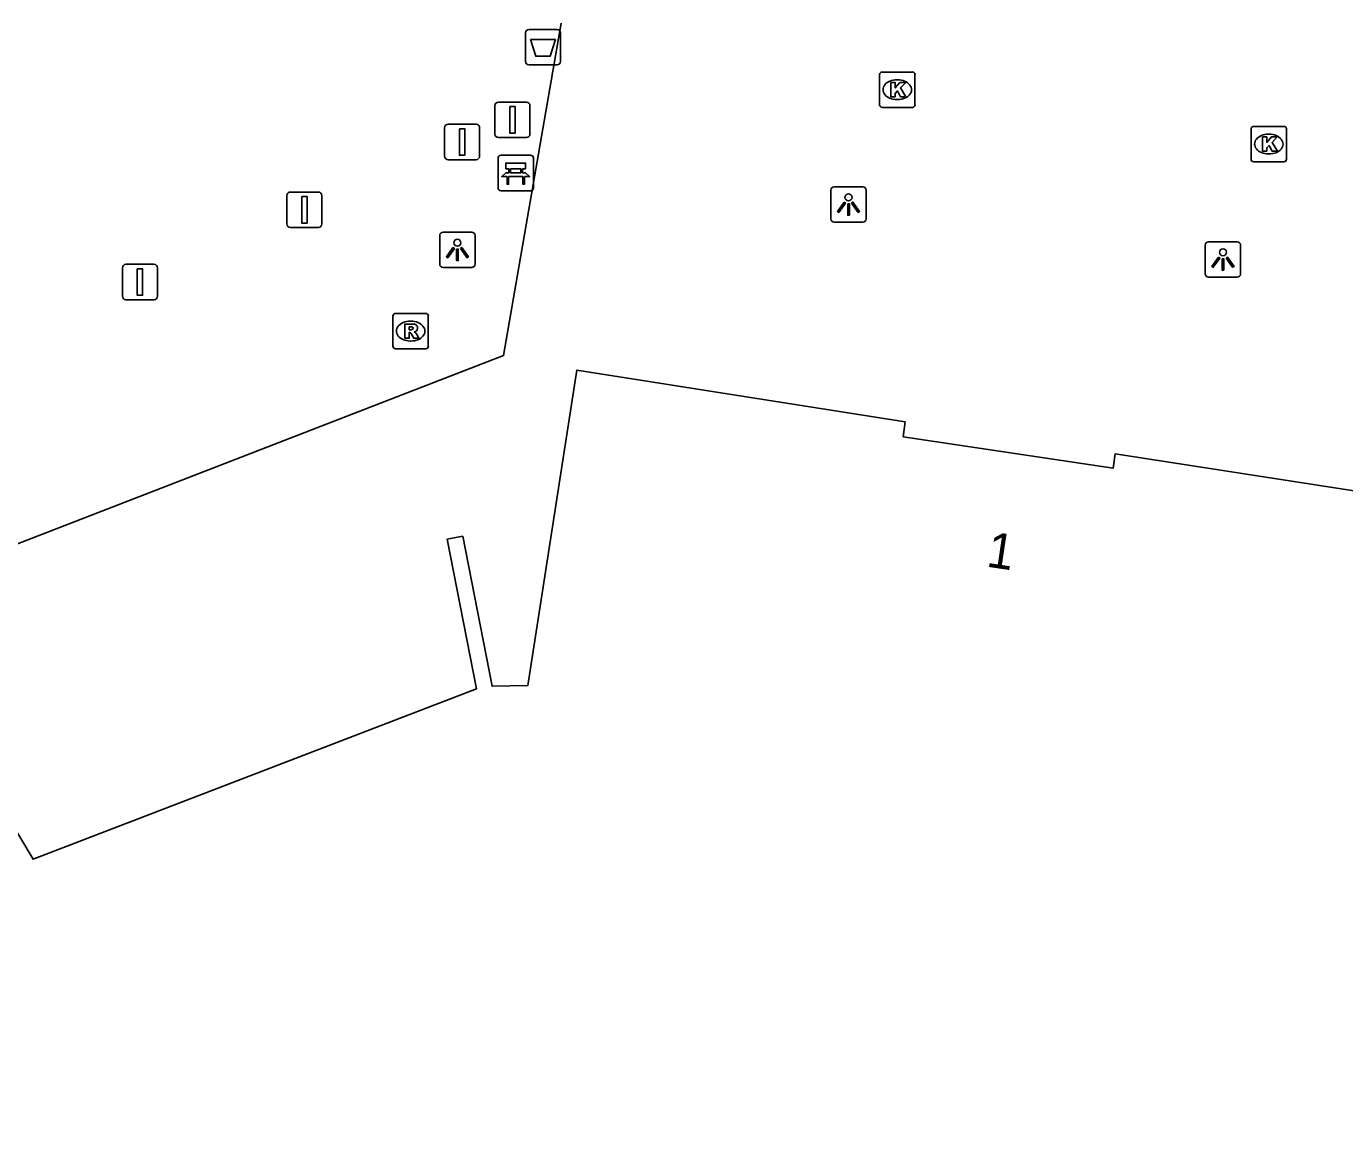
# Model space of a CAD drawing. Extents: x 161094 to 161705, y 379509 to 380907.
# Drawn here: x 161518.54 to 161555.75, y 380401.06 to 380432.35 of the extents above; entities that cross this region are included whole.
import ezdxf

# ---------------------------------------------------------------- set-up
doc = ezdxf.new("R2010")
doc.units = 0
for name, color, linetype in [('IMGEO_Afsluitpaal', 7, 'Continuous'), ('IMGEO_Afvalbak', 7, 'Continuous'), ('IMGEO_Bank', 7, 'Continuous'), ('IMGEO_Kolk', 7, 'Continuous'), ('IMGEO_Lichtpunt', 7, 'Continuous'), ('IMGEO_Pand', 7, 'Continuous'), ('IMGEO_Pand_nummerreeks', 7, 'Continuous'), ('IMGEO_Rioolput', 7, 'Continuous'), ('IMGEO_Vlaggenmast', 7, 'Continuous'), ('IMGEO_Voetpad_open', 7, 'Continuous')]:
    doc.layers.add(name, color=color, linetype=linetype)

msp = doc.modelspace()

# ---------------------------------------------------------------- linework, layer by layer
at = {"layer": 'IMGEO_Afsluitpaal'}
for p, q in [((161531.863, 380430.213), (161532.653, 380430.213)), ((161532.653, 380430.213), (161531.863, 380430.213)), ((161531.763, 380429.313), (161531.763, 380430.113)), ((161531.763, 380430.113), (161531.763, 380429.313)), ((161532.753, 380430.113), (161532.753, 380429.313)), ((161532.753, 380429.313), (161532.753, 380430.113)), ((161532.653, 380429.213), (161531.863, 380429.213)), ((161531.863, 380429.213), (161532.653, 380429.213))]:
    msp.add_line(p, q, dxfattribs=at)
msp.add_lwpolyline([(161532.183, 380430.088), (161532.333, 380430.088), (161532.333, 380429.338), (161532.183, 380429.338), (161532.183, 380430.088)], dxfattribs=at)
for centre, start, end in [((161531.863, 380430.113), 90, 180), ((161531.863, 380430.113), 90, 180), ((161532.653, 380430.113), 0, 90), ((161532.653, 380430.113), 360, 90), ((161531.863, 380429.313), 180, 270), ((161531.863, 380429.313), 180, 270), ((161532.653, 380429.313), 270, 0), ((161532.653, 380429.313), 270, 0)]:
    msp.add_arc(centre, 0.1, start, end, dxfattribs=at)
at = {"layer": 'IMGEO_Afvalbak'}
for p, q in [((161532.626, 380431.365), (161532.626, 380432.165)), ((161532.626, 380432.165), (161532.626, 380431.365)), ((161532.726, 380432.265), (161533.516, 380432.265)), ((161533.516, 380432.265), (161532.726, 380432.265)), ((161533.616, 380432.165), (161533.616, 380431.365)), ((161533.616, 380431.365), (161533.616, 380432.165)), ((161533.516, 380431.265), (161532.726, 380431.265)), ((161532.726, 380431.265), (161533.516, 380431.265))]:
    msp.add_line(p, q, dxfattribs=at)
msp.add_lwpolyline([(161532.769, 380431.979), (161533.473, 380431.979), (161533.324, 380431.509), (161532.918, 380431.509), (161532.769, 380431.979)], dxfattribs=at)
for centre, start, end in [((161532.726, 380432.165), 90, 180), ((161532.726, 380432.165), 90, 180), ((161533.516, 380432.165), 0, 90), ((161533.516, 380432.165), 360, 90), ((161532.726, 380431.365), 180, 270), ((161532.726, 380431.365), 180, 270), ((161533.516, 380431.365), 270, 0), ((161533.516, 380431.365), 270, 0)]:
    msp.add_arc(centre, 0.1, start, end, dxfattribs=at)
at = {"layer": 'IMGEO_Bank'}
for p, q in [((161531.926, 380428.713), (161532.767, 380428.713)), ((161532.767, 380428.713), (161531.926, 380428.713)), ((161531.851, 380427.788), (161531.851, 380428.629)), ((161531.851, 380428.629), (161531.851, 380427.788)), ((161532.16, 380428.219), (161532.16, 380428.325)), ((161532.204, 380428.325), (161532.204, 380428.219)), ((161532.492, 380428.331), (161532.21, 380428.331)), ((161532.498, 380428.219), (161532.498, 380428.325)), ((161532.542, 380428.325), (161532.542, 380428.219)), ((161532.851, 380428.638), (161532.851, 380427.797)), ((161532.851, 380427.797), (161532.851, 380428.638)), ((161532.548, 380428.111), (161532.155, 380428.111)), ((161532.21, 380428.213), (161532.492, 380428.213)), ((161532.776, 380427.713), (161531.935, 380427.713)), ((161531.935, 380427.713), (161532.776, 380427.713))]:
    msp.add_line(p, q, dxfattribs=at)
for points in [[(161532.154, 380428.331), (161532.068, 380428.331), (161532.068, 380428.492), (161532.631, 380428.492), (161532.631, 380428.331), (161532.548, 380428.331)], [(161532.098, 380428.111), (161531.956, 380428.111), (161532.068, 380428.213), (161532.154, 380428.213)], [(161532.148, 380428.104), (161532.148, 380427.897), (161532.105, 380427.897), (161532.105, 380428.104)], [(161532.548, 380428.213), (161532.631, 380428.213), (161532.743, 380428.111), (161532.604, 380428.111)], [(161532.598, 380428.104), (161532.598, 380427.897), (161532.554, 380427.897), (161532.554, 380428.104)]]:
    msp.add_lwpolyline(points, dxfattribs=at)
for centre, radius, start, end in [((161531.929, 380428.635), 0.0779, 92.4484, 184.2845), ((161531.929, 380428.635), 0.0779, 92.4484, 184.2845), ((161532.773, 380428.635), 0.0779, 2.4484, 94.2845), ((161532.773, 380428.635), 0.0779, 2.4484, 94.2845), ((161532.153, 380428.324), 0.00671, 2.8957, 87.1043), ((161532.21, 380428.324), 0.00671, 92.8957, 177.1043), ((161532.492, 380428.324), 0.00671, 2.8957, 87.1043), ((161532.549, 380428.324), 0.00671, 92.8957, 177.1043), ((161532.098, 380428.104), 0.00671, 2.8957, 87.1043), ((161532.155, 380428.104), 0.00671, 92.8957, 177.1043), ((161532.153, 380428.22), 0.00671, 272.8957, 357.1043), ((161532.21, 380428.22), 0.00671, 182.8957, 267.1043), ((161532.492, 380428.22), 0.00671, 272.8957, 357.1043), ((161532.549, 380428.22), 0.00671, 182.8957, 267.1043), ((161532.547, 380428.104), 0.00671, 2.8957, 87.1043), ((161532.604, 380428.104), 0.00671, 92.8957, 177.1043), ((161531.929, 380427.791), 0.0779, 182.4484, 274.2845), ((161531.929, 380427.791), 0.0779, 182.4484, 274.2845), ((161532.773, 380427.791), 0.0779, 272.4484, 4.2845), ((161532.773, 380427.791), 0.0779, 272.4484, 4.2845)]:
    msp.add_arc(centre, radius, start, end, dxfattribs=at)
at = {"layer": 'IMGEO_Kolk'}
for p, q in [((161542.621, 380430.138), (161542.621, 380430.99)), ((161542.696, 380431.064), (161543.548, 380431.064)), ((161543.622, 380430.99), (161543.622, 380430.138)), ((161543.109, 380430.844), (161543.134, 380430.844)), ((161543.132, 380430.284), (161543.107, 380430.284)), ((161543.548, 380430.064), (161542.696, 380430.064)), ((161553.11, 380428.603), (161553.11, 380429.455)), ((161553.185, 380429.529), (161554.037, 380429.529)), ((161554.111, 380429.455), (161554.111, 380428.603)), ((161553.598, 380429.309), (161553.623, 380429.309)), ((161553.621, 380428.749), (161553.596, 380428.749)), ((161554.037, 380428.529), (161553.185, 380428.529))]:
    msp.add_line(p, q, dxfattribs=at)
for points in [[(161542.621, 380430.138), (161542.621, 380430.99)], [(161542.696, 380431.064), (161543.548, 380431.064)], [(161543.622, 380430.99), (161543.622, 380430.138)], [(161542.942, 380430.764), (161543.065, 380430.764), (161543.065, 380430.613), (161543.195, 380430.764), (161543.359, 380430.764), (161543.213, 380430.613), (161543.366, 380430.364), (161543.214, 380430.364), (161543.129, 380430.528), (161543.065, 380430.461), (161543.065, 380430.364), (161542.942, 380430.364), (161542.942, 380430.764)], [(161543.548, 380430.064), (161542.696, 380430.064)], [(161553.11, 380428.603), (161553.11, 380429.455)], [(161553.185, 380429.529), (161554.037, 380429.529)], [(161554.111, 380429.455), (161554.111, 380428.603)], [(161553.431, 380429.229), (161553.554, 380429.229), (161553.554, 380429.078), (161553.684, 380429.229), (161553.848, 380429.229), (161553.702, 380429.078), (161553.855, 380428.829), (161553.703, 380428.829), (161553.618, 380428.993), (161553.554, 380428.926), (161553.554, 380428.829), (161553.431, 380428.829), (161553.431, 380429.229)], [(161554.037, 380428.529), (161553.185, 380428.529)]]:
    msp.add_lwpolyline(points, dxfattribs=at)
for centre, start, end in [((161542.698, 380430.988), 91.552, 178.448), ((161542.698, 380430.988), 91.552, 178.448), ((161543.546, 380430.988), 1.552, 88.448), ((161543.546, 380430.988), 1.552, 88.448), ((161542.698, 380430.14), 181.552, 268.448), ((161542.698, 380430.14), 181.552, 268.448), ((161543.546, 380430.14), 271.552, 358.448), ((161543.546, 380430.14), 271.552, 358.448), ((161553.187, 380429.453), 91.552, 178.448), ((161553.187, 380429.453), 91.552, 178.448), ((161554.035, 380429.453), 1.552, 88.448), ((161554.035, 380429.453), 1.552, 88.448), ((161553.187, 380428.605), 181.552, 268.448), ((161553.187, 380428.605), 181.552, 268.448), ((161554.035, 380428.605), 271.552, 358.448), ((161554.035, 380428.605), 271.552, 358.448)]:
    msp.add_arc(centre, 0.0765, start, end, dxfattribs=at)
for centre, major_axis, ratio, start_param, end_param in [((161543.108, 380430.564), (-0.387, 0.002), 0.722429, 4.712389, 7.853982), ((161543.133, 380430.564), (-0.39, 0.002), 0.717154, 1.570796, 4.712389), ((161553.597, 380429.029), (-0.387, 0.002), 0.722429, 4.712389, 7.853982), ((161553.622, 380429.029), (-0.39, 0.002), 0.717154, 1.570796, 4.712389)]:
    msp.add_ellipse(centre, major_axis=major_axis, ratio=ratio, start_param=start_param, end_param=end_param, dxfattribs=at)
at = {"layer": 'IMGEO_Lichtpunt'}
for p, q in [((161541.246, 380427.727), (161541.246, 380426.92)), ((161541.246, 380427.727), (161541.246, 380426.92)), ((161542.148, 380427.822), (161541.34, 380427.822)), ((161542.148, 380427.822), (161541.34, 380427.822)), ((161542.242, 380426.92), (161542.242, 380427.727)), ((161542.242, 380426.92), (161542.242, 380427.727)), ((161541.34, 380426.826), (161542.148, 380426.826)), ((161541.34, 380426.826), (161542.148, 380426.826)), ((161531.107, 380426.541), (161530.299, 380426.541)), ((161531.107, 380426.541), (161530.299, 380426.541)), ((161530.205, 380426.446), (161530.205, 380425.639)), ((161530.205, 380426.446), (161530.205, 380425.639)), ((161531.201, 380425.639), (161531.201, 380426.446)), ((161531.201, 380425.639), (161531.201, 380426.446)), ((161551.818, 380426.176), (161551.818, 380425.369)), ((161551.818, 380426.176), (161551.818, 380425.369)), ((161552.72, 380426.271), (161551.912, 380426.271)), ((161552.72, 380426.271), (161551.912, 380426.271)), ((161552.814, 380425.369), (161552.814, 380426.176)), ((161552.814, 380425.369), (161552.814, 380426.176)), ((161530.299, 380425.545), (161531.107, 380425.545)), ((161530.299, 380425.545), (161531.107, 380425.545)), ((161551.912, 380425.275), (161552.72, 380425.275)), ((161551.912, 380425.275), (161552.72, 380425.275))]:
    msp.add_line(p, q, dxfattribs=at)
for points in [[(161541.62, 380427.391), (161541.659, 380427.363), (161541.471, 380427.101), (161541.433, 380427.128), (161541.62, 380427.391)], [(161541.722, 380427.343), (161541.769, 380427.343), (161541.769, 380427.021), (161541.722, 380427.021), (161541.722, 380427.343)], [(161541.832, 380427.363), (161541.87, 380427.39), (161542.057, 380427.128), (161542.018, 380427.1), (161541.832, 380427.363)], [(161530.579, 380426.11), (161530.618, 380426.082), (161530.43, 380425.82), (161530.392, 380425.847), (161530.579, 380426.11)], [(161530.791, 380426.082), (161530.829, 380426.109), (161531.016, 380425.847), (161530.977, 380425.819), (161530.791, 380426.082)], [(161530.681, 380426.062), (161530.728, 380426.062), (161530.728, 380425.74), (161530.681, 380425.74), (161530.681, 380426.062)], [(161552.192, 380425.84), (161552.231, 380425.812), (161552.043, 380425.55), (161552.005, 380425.577), (161552.192, 380425.84)], [(161552.294, 380425.792), (161552.341, 380425.792), (161552.341, 380425.47), (161552.294, 380425.47), (161552.294, 380425.792)], [(161552.404, 380425.812), (161552.442, 380425.839), (161552.629, 380425.577), (161552.59, 380425.549), (161552.404, 380425.812)]]:
    msp.add_lwpolyline(points, dxfattribs=at)
for centre in [(161541.745, 380427.525), (161530.704, 380426.244), (161552.317, 380425.974)]:
    msp.add_circle(centre, 0.0994, dxfattribs=at)
for centre, start, end in [((161541.34, 380427.727), 90, 180), ((161541.34, 380427.727), 90, 180), ((161542.148, 380427.727), 0, 90), ((161542.148, 380427.727), 0, 90), ((161541.34, 380426.92), 180, 270), ((161541.34, 380426.92), 180, 270), ((161542.148, 380426.92), 270, 0), ((161542.148, 380426.92), 270, 360), ((161530.299, 380426.446), 90, 180), ((161530.299, 380426.446), 90, 180), ((161531.107, 380426.446), 0, 90), ((161531.107, 380426.446), 0, 90), ((161551.912, 380426.176), 90, 180), ((161551.912, 380426.176), 90, 180), ((161552.72, 380426.176), 0, 90), ((161552.72, 380426.176), 0, 90), ((161530.299, 380425.639), 180, 270), ((161530.299, 380425.639), 180, 270), ((161531.107, 380425.639), 270, 0), ((161531.107, 380425.639), 270, 360), ((161551.912, 380425.369), 180, 270), ((161551.912, 380425.369), 180, 270), ((161552.72, 380425.369), 270, 0), ((161552.72, 380425.369), 270, 360)]:
    msp.add_arc(centre, 0.0946, start, end, dxfattribs=at)
at = {"layer": 'IMGEO_Pand'}
msp.add_lwpolyline([(161572.534, 380403.556), (161572.222, 380403.897), (161570.561, 380402.435), (161568.999, 380401.06), (161558.595, 380409.43), (161560.648, 380413.202), (161560.248, 380413.425), (161558.15, 380409.628), (161557.225, 380409.976), (161558.567, 380418.844), (161549.278, 380420.286), (161549.217, 380419.881), (161543.293, 380420.766), (161543.349, 380421.185), (161534.077, 380422.646), (161532.695, 380413.746), (161531.682, 380413.721), (161530.856, 380417.957), (161530.412, 380417.872), (161531.24, 380413.643), (161518.726, 380408.834), (161516.54, 380412.485), (161516.143, 380412.236)], dxfattribs=at)
at = {"layer": 'IMGEO_Rioolput'}
for p, q in [((161528.957, 380424.248), (161529.809, 380424.248)), ((161528.882, 380423.322), (161528.882, 380424.174)), ((161529.37, 380424.028), (161529.395, 380424.028)), ((161529.883, 380424.174), (161529.883, 380423.322)), ((161529.809, 380423.248), (161528.957, 380423.248)), ((161529.393, 380423.468), (161529.368, 380423.468))]:
    msp.add_line(p, q, dxfattribs=at)
for points in [[(161528.957, 380424.248), (161529.809, 380424.248)], [(161528.882, 380423.322), (161528.882, 380424.174)], [(161529.471, 380423.946), (161529.219, 380423.948), (161529.219, 380423.548)], [(161529.397, 380423.867), (161529.343, 380423.867), (161529.343, 380423.786)], [(161529.883, 380424.174), (161529.883, 380423.322)], [(161529.219, 380423.548), (161529.343, 380423.548), (161529.343, 380423.71), (161529.354, 380423.71)], [(161529.343, 380423.786), (161529.395, 380423.786)], [(161529.401, 380423.681), (161529.472, 380423.548), (161529.612, 380423.548), (161529.547, 380423.674)], [(161529.809, 380423.248), (161528.957, 380423.248)]]:
    msp.add_lwpolyline(points, dxfattribs=at)
for centre, radius, start, end in [((161528.959, 380424.172), 0.0765, 91.552, 178.448), ((161528.959, 380424.172), 0.0765, 91.552, 178.448), ((161529.807, 380424.172), 0.0765, 1.552, 88.448), ((161529.807, 380424.172), 0.0765, 1.552, 88.448), ((161529.403, 380423.771), 0.0964, 77.0061, 93.1865), ((161529.417, 380423.828), 0.0378, 276.6634, 79.6772), ((161529.47, 380423.836), 0.109, 350.3612, 89.416), ((161529.353, 380423.657), 0.0533, 26.0293, 88.6989), ((161529.379, 380423.975), 0.19, 274.7715, 282.9687), ((161529.468, 380423.836), 0.112, 277.5842, 350.9817), ((161529.452, 380423.621), 0.108, 29.5134, 73.7905), ((161528.959, 380423.324), 0.0765, 181.552, 268.448), ((161528.959, 380423.324), 0.0765, 181.552, 268.448), ((161529.807, 380423.324), 0.0765, 271.552, 358.448), ((161529.807, 380423.324), 0.0765, 271.552, 358.448)]:
    msp.add_arc(centre, radius, start, end, dxfattribs=at)
for centre, major_axis, ratio, start_param, end_param in [((161529.369, 380423.748), (-0.387, 0.002), 0.722429, 4.712389, 7.853982), ((161529.394, 380423.748), (-0.39, 0.002), 0.717154, 1.570796, 4.712389)]:
    msp.add_ellipse(centre, major_axis=major_axis, ratio=ratio, start_param=start_param, end_param=end_param, dxfattribs=at)
at = {"layer": 'IMGEO_Vlaggenmast'}
for p, q in [((161530.342, 380428.688), (161530.342, 380429.488)), ((161530.342, 380429.488), (161530.342, 380428.688)), ((161530.442, 380429.588), (161531.232, 380429.588)), ((161531.232, 380429.588), (161530.442, 380429.588)), ((161531.332, 380429.488), (161531.332, 380428.688)), ((161531.332, 380428.688), (161531.332, 380429.488)), ((161531.232, 380428.588), (161530.442, 380428.588)), ((161530.442, 380428.588), (161531.232, 380428.588)), ((161525.888, 380426.775), (161525.888, 380427.575)), ((161525.888, 380427.575), (161525.888, 380426.775)), ((161525.988, 380427.675), (161526.778, 380427.675)), ((161526.778, 380427.675), (161525.988, 380427.675)), ((161526.878, 380427.575), (161526.878, 380426.775)), ((161526.878, 380426.775), (161526.878, 380427.575)), ((161526.778, 380426.675), (161525.988, 380426.675)), ((161525.988, 380426.675), (161526.778, 380426.675)), ((161521.248, 380424.734), (161521.248, 380425.534)), ((161521.248, 380425.534), (161521.248, 380424.734)), ((161521.348, 380425.634), (161522.138, 380425.634)), ((161522.138, 380425.634), (161521.348, 380425.634)), ((161522.238, 380425.534), (161522.238, 380424.734)), ((161522.238, 380424.734), (161522.238, 380425.534)), ((161522.138, 380424.634), (161521.348, 380424.634)), ((161521.348, 380424.634), (161522.138, 380424.634))]:
    msp.add_line(p, q, dxfattribs=at)
for points in [[(161530.762, 380429.463), (161530.912, 380429.463), (161530.912, 380428.713), (161530.762, 380428.713), (161530.762, 380429.463)], [(161526.308, 380427.55), (161526.458, 380427.55), (161526.458, 380426.8), (161526.308, 380426.8), (161526.308, 380427.55)], [(161521.668, 380425.509), (161521.818, 380425.509), (161521.818, 380424.759), (161521.668, 380424.759), (161521.668, 380425.509)]]:
    msp.add_lwpolyline(points, dxfattribs=at)
for centre, start, end in [((161530.442, 380429.488), 90, 180), ((161530.442, 380429.488), 90, 180), ((161531.232, 380429.488), 0, 90), ((161531.232, 380429.488), 360, 90), ((161530.442, 380428.688), 180, 270), ((161530.442, 380428.688), 180, 270), ((161531.232, 380428.688), 270, 0), ((161531.232, 380428.688), 270, 0), ((161525.988, 380427.575), 90, 180), ((161525.988, 380427.575), 90, 180), ((161526.778, 380427.575), 0, 90), ((161526.778, 380427.575), 360, 90), ((161525.988, 380426.775), 180, 270), ((161525.988, 380426.775), 180, 270), ((161526.778, 380426.775), 270, 0), ((161526.778, 380426.775), 270, 0), ((161521.348, 380425.534), 90, 180), ((161521.348, 380425.534), 90, 180), ((161522.138, 380425.534), 0, 90), ((161522.138, 380425.534), 360, 90), ((161521.348, 380424.734), 180, 270), ((161521.348, 380424.734), 180, 270), ((161522.138, 380424.734), 270, 0), ((161522.138, 380424.734), 270, 0)]:
    msp.add_arc(centre, 0.1, start, end, dxfattribs=at)
at = {"layer": 'IMGEO_Voetpad_open'}
msp.add_lwpolyline([(161513.716, 380415.972), (161532.008, 380423.057), (161533.633, 380432.441)], dxfattribs=at)

# ---------------------------------------------------------------- texts
at = {"layer": 'IMGEO_Pand_nummerreeks'}
msp.add_text('1', height=1, rotation=351.503, dxfattribs=at).set_placement((161545.611, 380417.103))

doc.saveas('drawing.dxf')
